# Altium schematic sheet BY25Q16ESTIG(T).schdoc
size 127 x 101 mm
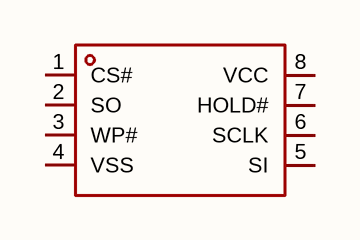
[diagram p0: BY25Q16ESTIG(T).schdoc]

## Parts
U?  by25q16estig(t)  [SOP-8_L4.9-W3.9-P1.27-LS6.0-BL]  (value not drawn)

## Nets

Not connected (* = marked no-connect by the designer): U? 1(CS#) 2(SO) 3(WP#) 4(VSS) 5(SI) 6(SCLK) 7(HOLD#) 8(VCC)

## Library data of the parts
U? = by25q16estig(t): 接口类型:SPI;存储容量:16Mbit;时钟频率(fc):108MHz;; Manufacturer: BOYAMICRO(博雅); AddInBom: yes; ModelId: 75c24a7891ee4dd6bdac16a7163ff87e; ModelName: SOP-8_L4.9-W3.9-P1.27-LS6.0-BL-1; ModelTransform: 192.913,236.22,0,0,0,0,-0.393,2.749,0; Interface: SPI; Memory Size: 16Mbit; Clock Frequency: 108MHz; Voltage - Supply: 2.7V~3.6V; Standby Supply Current: 2.5uA; Program / Erase Cycles: 100000次; Page Programming Time (Tpp): 160us; Data Retention - TDR (Year): 20年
